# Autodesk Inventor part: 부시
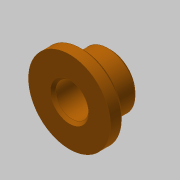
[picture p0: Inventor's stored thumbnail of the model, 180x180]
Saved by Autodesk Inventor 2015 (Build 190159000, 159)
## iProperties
Created: 2016-02
Part Number: 부시
Material: 스테인리스강
Document SubType Name: Modeling
Designer: mduedu
Density: 8.08 g/cm^3
Mass: 39.4553 g
Surface Area: 27.3717 cm^2
Volume: 4.88308 cm^3
Appearance: 주황색
Author: mduedu
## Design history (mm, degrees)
sketch "스케치1"
  geometry: C1 r 15 at (0, 0); 1 further point
  constraints: 1 centre point, 1 coincident
  dimensions: "d0" = 30 diameter of C1
extrude "돌출1" new body sketch "스케치1" distance "d1" = 5; taper "d2" = 0 deg
sketch "스케치2"
  geometry: C1 r 10 at (0, 0); 1 further point
  constraints: 1 centre point, 1 coincident
  dimensions: "d3" = 20 diameter of C1
extrude "돌출2" join sketch "스케치2" distance "d4" = 10; taper "d5" = 0 deg
hole "구멍1" diameter "d8" = 12; stored, may be unused: countersink angle "d12" = 90 deg, drill point angle "d14" = 118 deg; dims "d9" = 6, "d10" = 4, "d11" = 2, "d13" = 8, "d15" = 10, "d16" = 10
chamfer "모따기1" distance "d17" = 1; stored, may be unused: second distance "d18" = 2, angle "d19" = 45 deg
chamfer "모따기2" distance "d20" = 1; stored, may be unused: second distance "d21" = 2, angle "d22" = 45 deg
chamfer "모따기3" distance "d23" = 1; stored, may be unused: second distance "d24" = 2, angle "d25" = 45 deg
node "솔리드1"
